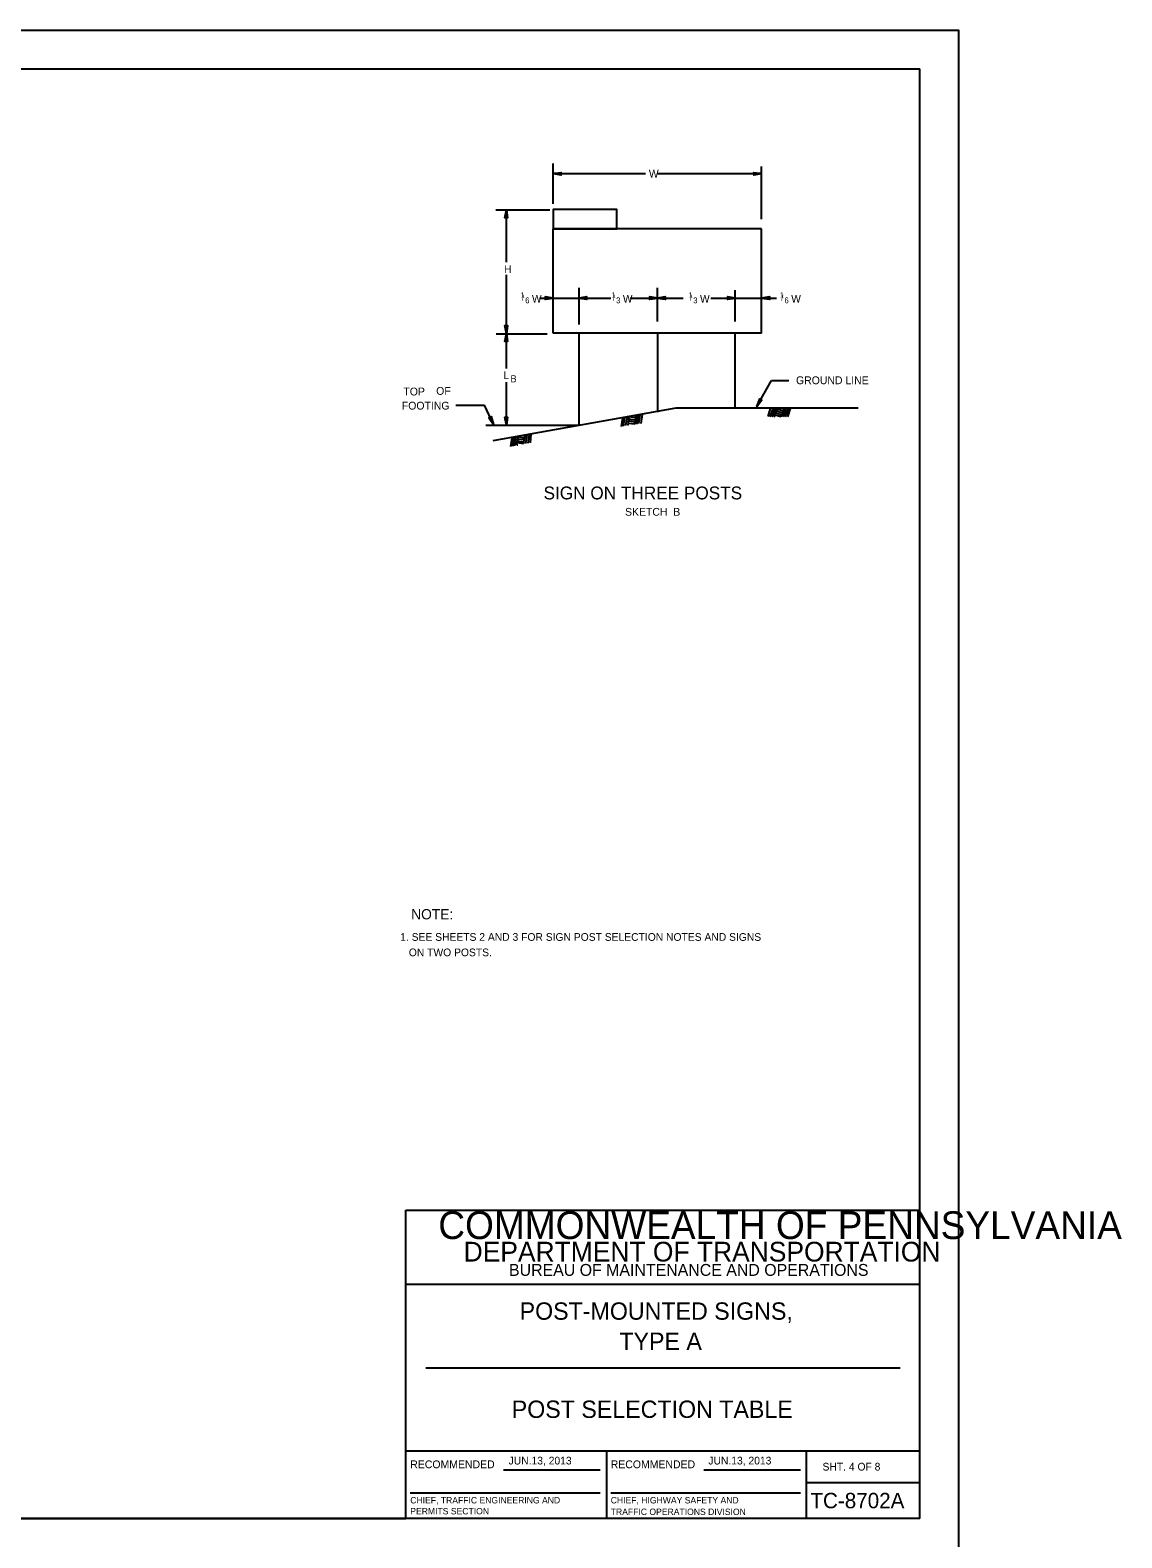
# Model space of a CAD drawing. Extents: x 637580 to 641008, y 294594 to 295782.
# Drawn here: x 640583 to 641008, y 295195 to 295782 of the extents above; entities that cross this region are included whole.
import ezdxf

# ---------------------------------------------------------------- set-up
doc = ezdxf.new("R2010")
doc.units = 0
for name, color, linetype in [('1', 7, 'Continuous'), ('2', 7, 'Continuous'), ('PLT-BNDY', 7, 'Continuous')]:
    doc.layers.add(name, color=color, linetype=linetype)

msp = doc.modelspace()

# ---------------------------------------------------------------- linework, layer by layer
at = {"layer": '1'}
for p, q in [((640143.31, 295766.63), (640929.31, 295766.63)), ((640929.31, 295202.63), (640929.31, 295766.63)), ((640786.58, 295714.03), (640786.58, 295729.78)), ((640786.58, 295725.9), (640822.58, 295725.9)), ((640827.21, 295725.9), (640867.71, 295725.9)), ((640867.71, 295708.15), (640867.71, 295728.65)), ((640764.33, 295711.78), (640785.33, 295711.78)), ((640768.46, 295691.4), (640768.46, 295711.78)), ((640786.58, 295663.78), (640786.58, 295704.4)), ((640867.71, 295704.4), (640786.58, 295704.4)), ((640867.71, 295663.78), (640867.71, 295704.4)), ((640768.46, 295663.53), (640768.46, 295686.4)), ((640796.71, 295667.15), (640796.71, 295681.4)), ((640827.21, 295668.28), (640827.21, 295681.4)), ((640857.46, 295668.28), (640857.46, 295680.53)), ((640781.33, 295677.4), (640786.58, 295677.4)), ((640786.58, 295677.4), (640796.21, 295677.4)), ((640796.71, 295677.4), (640809.08, 295677.4)), ((640816.58, 295677.4), (640827.21, 295677.4)), ((640827.21, 295677.4), (640837.21, 295677.4)), ((640847.96, 295677.4), (640857.46, 295677.4)), ((640857.46, 295677.4), (640867.71, 295677.4)), ((640867.71, 295677.4), (640873.46, 295677.4)), ((640764.46, 295663.53), (640784.21, 295663.53)), ((640768.46, 295650.03), (640768.46, 295663.53)), ((640867.71, 295663.78), (640786.58, 295663.78)), ((640796.71, 295627.9), (640796.71, 295663.78)), ((640827.21, 295663.78), (640827.21, 295633.03)), ((640857.46, 295634.4), (640857.46, 295663.78)), ((640768.46, 295627.9), (640768.46, 295644.65)), ((640865.83, 295635.28), (640871.58, 295645.28)), ((640871.58, 295645.28), (640878.33, 295645.28)), ((640748.71, 295635.78), (640759.83, 295635.78)), ((640763.33, 295628.28), (640759.83, 295635.78)), ((640834.33, 295634.53), (640763.08, 295621.9)), ((640816.08, 295631.28), (640815.58, 295627.9)), ((640818.71, 295631.65), (640818.21, 295628.4)), ((640818.71, 295631.4), (640818.33, 295631.53)), ((640819.58, 295631.9), (640819.08, 295628.4)), ((640820.33, 295631.9), (640819.83, 295628.65)), ((640821.21, 295632.15), (640820.71, 295628.65)), ((640905.21, 295634.53), (640834.33, 295634.53)), ((640871.08, 295634.4), (640870.08, 295631.28)), ((640872.08, 295634.4), (640870.83, 295631.15)), ((640872.83, 295634.4), (640871.71, 295631.15)), ((640873.71, 295634.4), (640872.46, 295631.15)), ((640872.96, 295631.15), (640872.58, 295631.28)), ((640875.33, 295631.15), (640872.83, 295631.9)), ((640875.46, 295631.9), (640873.08, 295632.78)), ((640875.71, 295632.65), (640873.46, 295633.53)), ((640876.08, 295633.4), (640873.71, 295634.28)), ((640876.33, 295634.4), (640875.33, 295631.15)), ((640876.33, 295634.28), (640875.83, 295634.4)), ((640877.08, 295634.4), (640876.08, 295631.15)), ((640878.08, 295634.4), (640876.83, 295631.15)), ((640878.83, 295634.4), (640877.83, 295631.15)), ((640760.33, 295627.9), (640796.71, 295627.9)), ((640813.58, 295630.78), (640813.08, 295627.4)), ((640814.33, 295631.03), (640813.83, 295627.53)), ((640815.21, 295631.03), (640814.71, 295627.78)), ((640815.96, 295628.03), (640815.58, 295628.03)), ((640818.33, 295628.4), (640815.71, 295628.65)), ((640818.33, 295629.15), (640815.83, 295629.65)), ((640818.46, 295629.9), (640815.96, 295630.28)), ((640818.58, 295630.78), (640816.08, 295631.15)), ((640770.46, 295623.03), (640769.96, 295619.65)), ((640771.33, 295623.15), (640770.71, 295619.78)), ((640772.08, 295623.4), (640771.58, 295619.9)), ((640772.96, 295623.53), (640772.33, 295620.15)), ((640772.83, 295620.15), (640772.46, 295620.15)), ((640775.08, 295620.65), (640772.58, 295621.03)), ((640775.08, 295621.4), (640772.71, 295621.78)), ((640775.33, 295622.28), (640772.83, 295622.53)), ((640775.46, 295622.9), (640772.96, 295623.4)), ((640775.58, 295623.9), (640774.96, 295620.65)), ((640775.58, 295623.9), (640775.08, 295623.9)), ((640776.33, 295624.03), (640775.83, 295620.78)), ((640777.21, 295624.28), (640776.71, 295620.9)), ((640777.96, 295624.4), (640777.58, 295621.03)), ((640729.31, 295202.63), (640729.31, 295322.63)), ((640729.31, 295322.63), (640929.31, 295322.63)), ((640929.31, 295293.63), (640729.31, 295293.63)), ((640737.06, 295261.31), (640921.56, 295261.31)), ((640729.31, 295229), (640929.31, 295229)), ((640807.31, 295229), (640807.31, 295202.63)), ((640885.19, 295202.63), (640885.19, 295229)), ((640767.24, 295221.57), (640804.87, 295221.57)), ((640845.24, 295221.57), (640882.87, 295221.57)), ((640885.19, 295216.63), (640929.31, 295216.63)), ((640730.99, 295212.68), (640804.87, 295212.68)), ((640808.99, 295212.68), (640882.87, 295212.68)), ((640929.31, 295202.63), (640143.31, 295202.63)), ((640143.31, 295202.63), (640729.31, 295202.63))]:
    msp.add_line(p, q, dxfattribs=at)
for points in [[(640789.58, 295725.4), (640789.33, 295725.65), (640786.58, 295725.9), (640789.58, 295725.4), (640789.71, 295725.28), (640786.58, 295725.9), (640789.33, 295725.9), (640789.46, 295726.03), (640786.58, 295725.9), (640789.71, 295726.28), (640789.46, 295726.03)], [(640864.71, 295726.03), (640864.83, 295725.9), (640867.71, 295725.9), (640864.71, 295726.03), (640864.71, 295726.28), (640867.71, 295725.9), (640864.83, 295725.65), (640864.83, 295725.4), (640867.71, 295725.9), (640864.71, 295725.28), (640864.83, 295725.4)], [(640767.96, 295708.9), (640768.21, 295708.9), (640768.46, 295711.78), (640767.96, 295708.9), (640767.83, 295708.65), (640768.46, 295711.78), (640768.58, 295708.9), (640768.71, 295708.9), (640768.46, 295711.78), (640768.83, 295708.65), (640768.71, 295708.9)], [(640783.58, 295677.9), (640783.71, 295677.65), (640786.58, 295677.4), (640783.58, 295677.9), (640783.46, 295677.9), (640786.58, 295677.4), (640783.71, 295677.28), (640783.58, 295677.03), (640786.58, 295677.4), (640783.46, 295676.9), (640783.58, 295677.03)], [(640799.58, 295677.03), (640799.46, 295677.28), (640796.71, 295677.4), (640799.58, 295677.03), (640799.71, 295676.9), (640796.71, 295677.4), (640799.46, 295677.65), (640799.58, 295677.9), (640796.71, 295677.4), (640799.71, 295677.9), (640799.58, 295677.9)], [(640824.21, 295677.9), (640824.33, 295677.65), (640827.21, 295677.4), (640824.21, 295677.9), (640824.08, 295677.9), (640827.21, 295677.4), (640824.33, 295677.28), (640824.21, 295677.03), (640827.21, 295677.4), (640824.08, 295676.9), (640824.21, 295677.03)], [(640830.21, 295677.03), (640829.96, 295677.28), (640827.21, 295677.4), (640830.21, 295677.03), (640830.33, 295676.9), (640827.21, 295677.4), (640829.96, 295677.65), (640830.21, 295677.9), (640827.21, 295677.4), (640830.33, 295677.9), (640830.21, 295677.9)], [(640854.58, 295677.9), (640854.71, 295677.65), (640857.46, 295677.4), (640854.58, 295677.9), (640854.46, 295677.9), (640857.46, 295677.4), (640854.71, 295677.28), (640854.58, 295677.03), (640857.46, 295677.4), (640854.46, 295676.9), (640854.58, 295677.03)], [(640870.71, 295677.03), (640870.58, 295677.28), (640867.71, 295677.4), (640870.71, 295677.03), (640870.83, 295676.9), (640867.71, 295677.4), (640870.58, 295677.65), (640870.71, 295677.9), (640867.71, 295677.4), (640870.83, 295677.9), (640870.71, 295677.9)], [(640768.83, 295666.53), (640768.58, 295666.4), (640768.46, 295663.53), (640768.83, 295666.53), (640768.83, 295666.78), (640768.46, 295663.53), (640768.21, 295666.4), (640767.96, 295666.53), (640768.46, 295663.53), (640767.83, 295666.78), (640767.96, 295666.53)], [(640767.96, 295660.65), (640768.21, 295660.78), (640768.46, 295663.53), (640767.96, 295660.65), (640767.83, 295660.53), (640768.46, 295663.53), (640768.58, 295660.78), (640768.71, 295660.65), (640768.46, 295663.53), (640768.83, 295660.53), (640768.71, 295660.65)], [(640867.71, 295637.65), (640867.33, 295637.65), (640865.83, 295635.28), (640867.71, 295637.65), (640867.83, 295637.65), (640865.83, 295635.28), (640867.08, 295637.78), (640866.96, 295638.03), (640865.83, 295635.28), (640866.96, 295638.15), (640866.96, 295638.03)], [(640762.46, 295631.03), (640762.33, 295630.78), (640763.33, 295628.28), (640762.46, 295631.03), (640762.46, 295631.28), (640763.33, 295628.28), (640762.08, 295630.65), (640761.71, 295630.65), (640763.33, 295628.28), (640761.58, 295630.78), (640761.71, 295630.65)], [(640768.83, 295630.9), (640768.58, 295630.78), (640768.46, 295627.9), (640768.83, 295630.9), (640768.83, 295631.03), (640768.46, 295627.9), (640768.21, 295630.78), (640767.96, 295630.78), (640768.46, 295627.9), (640767.83, 295631.03), (640767.96, 295630.78)]]:
    msp.add_lwpolyline(points, dxfattribs=at)
msp.add_lwpolyline([(640811.33, 295704.4), (640811.33, 295711.9), (640786.58, 295711.9), (640786.58, 295704.4)], close=True, dxfattribs=at)
at = {"layer": 'PLT-BNDY'}
msp.add_lwpolyline([(640103.31, 295781.63), (640944.31, 295781.63), (640944.31, 295187.63), (640103.31, 295187.63)], close=True, dxfattribs=at)

# ---------------------------------------------------------------- texts
at = {"layer": '1'}
for s, height, p in [('W', 3.04, (640823.83, 295724.28)), ('H', 3.04, (640767.46, 295687.15)), ('1', 2, (640773.96, 295677.65)), ('/', 2.25, (640774.46, 295676.4)), ('W', 3, (640778.33, 295675.65)), ('1', 2, (640809.33, 295677.65)), ('/', 2.25, (640809.83, 295676.4)), ('W', 3, (640813.71, 295675.65)), ('1', 2, (640839.33, 295677.65)), ('/', 2.25, (640839.83, 295676.4)), ('W', 3, (640843.71, 295675.65)), ('1', 2, (640874.83, 295677.65)), ('/', 2.25, (640875.33, 295676.4)), ('W', 3, (640879.21, 295675.65)), ('6', 2.25, (640775.71, 295675.4)), ('3', 2.25, (640811.08, 295675.4)), ('3', 2.25, (640841.08, 295675.4)), ('6', 2.25, (640876.58, 295675.4)), ('L', 3.04, (640767.21, 295645.9)), ('B', 2.73, (640769.96, 295644.65)), ('GROUND LINE', 3.0427, (640881.08, 295643.9)), ('FOOTING', 3.044, (640727.71, 295634.03)), ('TOP', 3.043, (640728.33, 295639.53)), ('OF', 3.043, (640741.08, 295639.78)), ('SKETCH  B', 3.044, (640814.56, 295592.73)), (' 1. SEE SHEETS 2 AND 3 FOR SIGN POST SELECTION NOTES AND SIGNS', 3, (640725.97, 295427.37)), ('    ON TWO POSTS.', 3, (640725.97, 295421.37)), ('COMMONWEALTH OF PENNSYLVANIA', 10.7828, (640741.9, 295311.36)), ('DEPARTMENT OF TRANSPORTATION', 7.6837, (640751.76, 295302.61)), ('BUREAU OF MAINTENANCE AND OPERATIONS', 4.6253, (640769.41, 295297.04)), ('POST-MOUNTED SIGNS,', 6.75, (640773.54, 295279.97)), ('TYPE A', 6.75, (640812.35, 295268.22)), ('POST SELECTION TABLE', 6.75, (640770.47, 295241.78)), ('RECOMMENDED', 3.048, (640730.99, 295222.2)), ('RECOMMENDED', 3.048, (640808.99, 295222.2)), ('SHT. 4 OF 8', 3, (640891.4, 295221.31)), ('CHIEF, TRAFFIC ENGINEERING AND', 2.5, (640730.99, 295208.51)), ('CHIEF, HIGHWAY SAFETY AND', 2.5, (640808.99, 295208.51)), ('TC-8702A', 6, (640886.68, 295206.63)), ('PERMITS SECTION', 2.5, (640730.99, 295204.26)), ('TRAFFIC OPERATIONS DIVISION', 2.5, (640808.99, 295204.01))]:
    msp.add_text(s, height=height, dxfattribs=at).set_placement(p)
at = {"layer": '2'}
for s, height, p in [('SIGN ON THREE POSTS', 5, (640782.85, 295599.09)), ('NOTE:', 4.003, (640731.35, 295435.71)), ('JUN.13, 2013', 3, (640769.25, 295223.67)), ('JUN.13, 2013', 3, (640846.97, 295223.67))]:
    msp.add_text(s, height=height, dxfattribs=at).set_placement(p)

doc.saveas('drawing.dxf')
